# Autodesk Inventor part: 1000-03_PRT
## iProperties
Created: 2007-03
Part Number: 1000-03_PRT
Document SubType Name: Modeling
Designer: Andy Moles
Material: Rubber
Mass: 0.0573632 g
Surface Area: 2.54827 cm^2
Volume: 0.0616809 cm^3
Density: 0.93 g/cm^3
Author: Andy Moles
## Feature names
1. Base1
